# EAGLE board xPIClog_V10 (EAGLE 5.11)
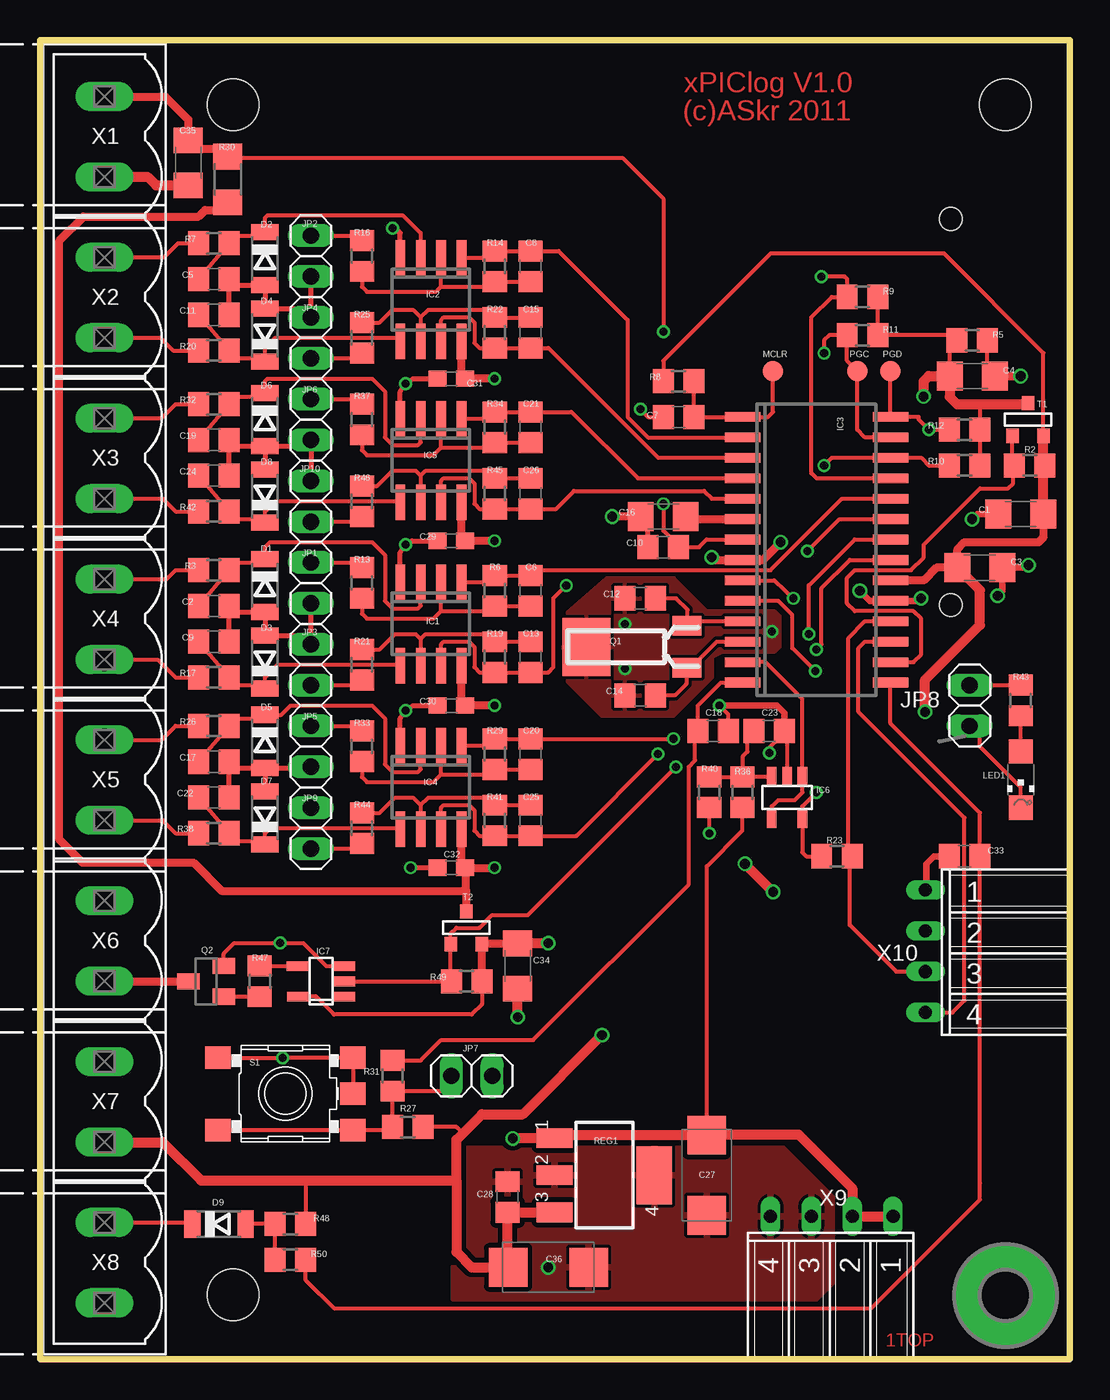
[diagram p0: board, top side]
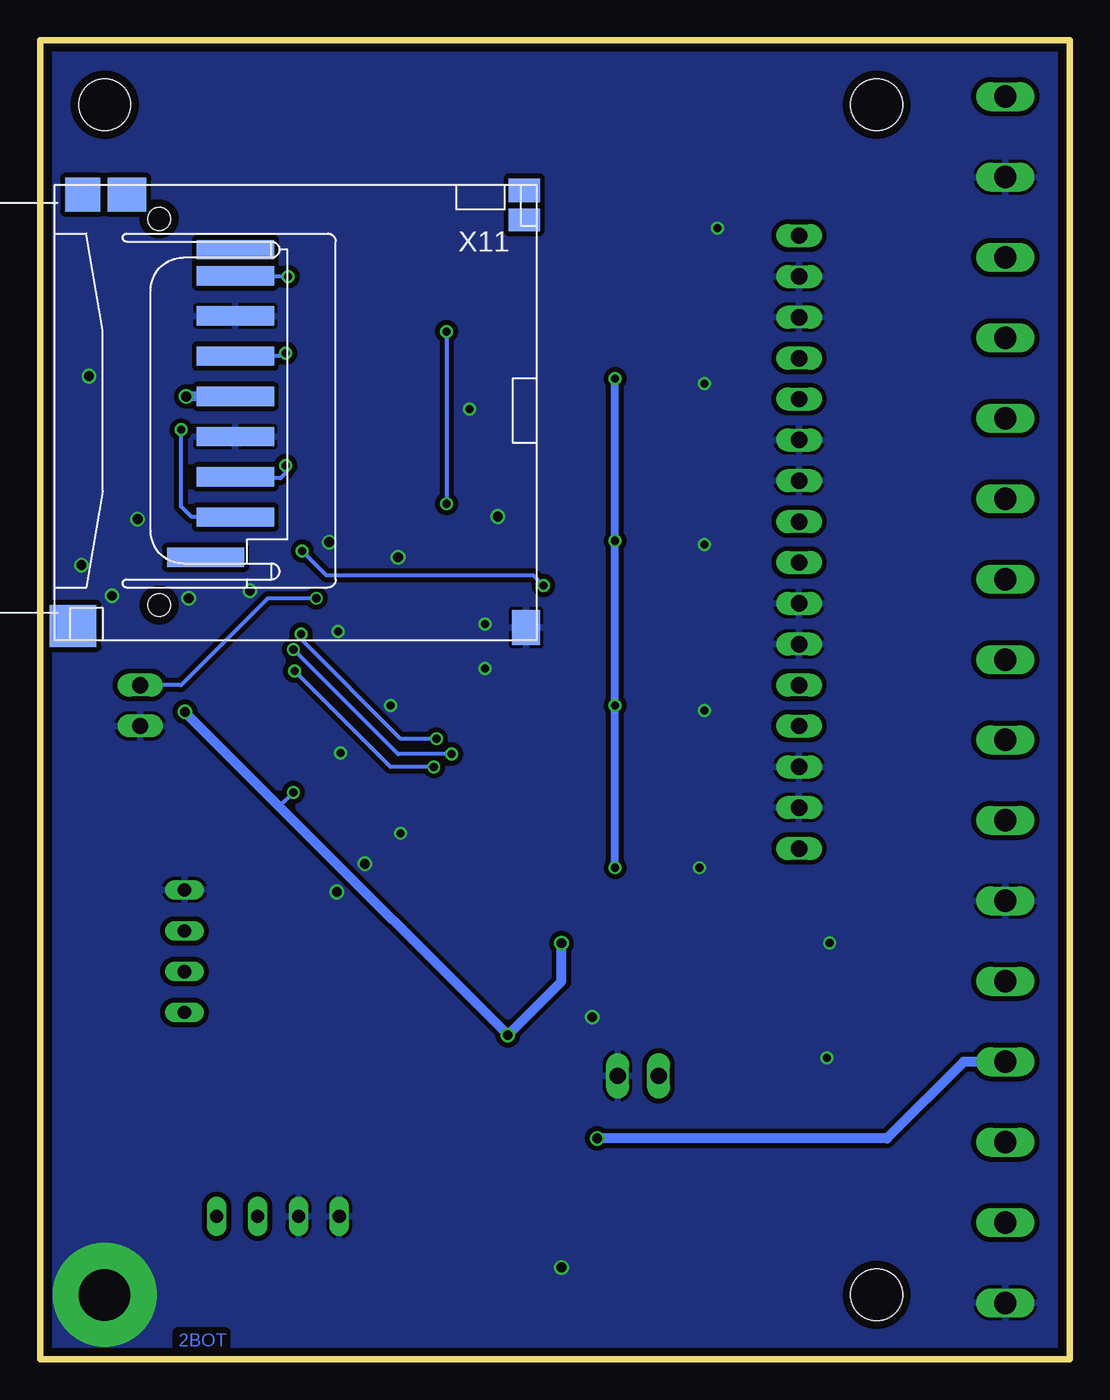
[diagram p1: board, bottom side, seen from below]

Size 64 x 82 mm. Coordinates in mm from the lower left corner, seen from the top.
Outline: 0,0 0,82 64,82 64,0 0,0
Copper layers (1*16): Top 0.035mm / dielectric 1.5mm / Bottom 0.035mm
Design rules "pcb-pool-2009": minimum track width 6mil, minimum drill 12mil, track to track 6mil, track to pad 6mil, pad to pad 6mil, via to via 6mil, smd to smd 6mil, copper to edge 20mil, drill to drill 8mil, minimum pad ring 8mil, minimum via ring 6mil, stop-mask expansion 3mil, vias tented up to drill 0mil, thermal gap 8mil
Holes 3.2 mm at 12,78 60,78 12,4
bRestrict: 3 lines

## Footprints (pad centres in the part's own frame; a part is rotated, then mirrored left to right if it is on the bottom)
C1206 = smd 1.6 x 1.8: 1 -1.4,0; 2 1.4,0
C0805 = smd 1.3 x 1.5: 1 -0.95,0; 2 0.95,0
SMC_C = smd 2.4 x 2.4: + -2.5,0; - 2.5,0
C0603 = smd 1.1 x 1: 1 -0.85,0; 2 0.85,0
SOD80-R = smd 1 x 1.7: A 1.65,0; C -1.65,0
SO08 = smd 0.6 x 2.2: 1 -1.905,-2.6; 2 -0.635,-2.6; 3 0.635,-2.6; 4 1.905,-2.6; 5 1.905,2.6; 6 0.635,2.6; 7 -0.635,2.6; 8 -1.905,2.6
AKKI_SO28W = smd 0.6 x 2.2: 1 -8.255,-4.6; 2 -6.985,-4.6; 3 -5.715,-4.6; 4 -4.445,-4.6; 5 -3.175,-4.6; 6 -1.905,-4.6; 7 -0.635,-4.6; 8 0.635,-4.6; 9 1.905,-4.6; 10 3.175,-4.6; 11 4.445,-4.6; 12 5.715,-4.6; 13 6.985,-4.6; 14 8.255,-4.6; 15 8.255,4.6; 16 6.985,4.6; 17 5.715,4.6; 18 4.445,4.6; 19 3.175,4.6; 20 1.905,4.6; 21 0.635,4.6; 22 -0.635,4.6; 23 -1.905,4.6; 24 -3.175,4.6; 25 -4.445,4.6; 26 -5.715,4.6; 27 -6.985,4.6; 28 -8.255,4.6
SOT23-5 = smd 0.6 x 1.2: 1 -0.95,-1.306; 2 0,-1.306; 3 0.95,-1.306; 4 0.95,1.306; 5 -0.95,1.306
AKKI_SOT235W = smd 0.6 x 1.4: 1 -0.95,-1.406; 2 0,-1.406; 3 0.95,-1.406; 5 -0.95,1.406 | smd 0.6 x 1.5: 4 0.95,1.406
1X02 = drill 1.016 long: 1 -1.27,0; 2 1.27,0
CHIPLED_1206 = smd 1.5 x 1.5: A 0,-1.75; C 0,1.75
B1,27 = smd 1.27 x 1.27: TP 0,0
AKKI_QUARTZ_MS1V-T1K = smd 1.8 x 1.2: 1 2.9,-1.3; 2 2.9,1.3 | smd 3 x 3.6: CASE -3.35,0
SOT23 = smd 1 x 1.4: 1 -0.95,-1.1; 2 0.95,-1.1; 3 0,1.1
R0805 = smd 1.3 x 1.5: 1 -0.95,0; 2 0.95,0
R1206 = smd 1.6 x 1.803: 1 -1.422,0; 2 1.422,0
AKKI_SOT223_4PIN = smd 1.219 x 2.235: 1 -2.311,-3.099; 2 0,-3.099; 3 2.311,-3.099 | smd 3.6 x 2.2: 4 0,3.099
SKHMPXE010 = smd 1.6 x 1.4: 1 -4.2,2.25; 2 4.2,2.25; 3 -4.2,-2.25; 4 4.2,-2.25; 5 4.2,0
SOT-23 = smd 0.787 x 0.889: 1 0.025,-1.016; 2 -0.94,1.016; 3 0.991,1.016
MSTBV2 = drill 1.397 long: 1 -2.5,0; 2 2.5,0
AKKI_FH1X4 = drill 0.813 long: 1 -5.08,0; 2 -2.54,0; 3 0,0; 4 2.54,0
AKKI_6173PACK2 = smd 4.8 x 1.2: P1 18.935,21.035; P2 18.935,18.535; P3 18.935,16.035; P4 18.935,13.535; P5 18.935,11.035; P6 18.935,8.535; P7 18.935,6.035; P8 18.935,4.41; P9 20.785,23.535 | smd 1.95 x 1.4: P_CD 0.975,2.55 | smd 1.95 x 1.45: P_COM 0.975,0.725 | smd 2.2 x 2.1: P_WP 28.425,1 | smd 1.75 x 2.2: PG1 0.875,27.9 | smd 2.9 x 2.6: PG2 29.025,27.8 | smd 2.4 x 2.1: PG3 25.675,1 | hole 1.4: 23.675,26.5; 23.675,2.5

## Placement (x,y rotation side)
C1  22u/6V3  [C1206]  60.96,52.55 0 top
C2  100n  [C0805]  10.79,46.83 0 top
C3  10u/6V3  [C1206]  58.42,49.21 180 top
C4  1u/6V3  [C1206]  57.94,61.12 0 top
C5  100n  [C0805]  10.8,67.15 0 top
C6  1n  [C0805]  30.48,47.78 90 top
C7  100n(*1*)  [C0805]  39.69,58.58 0 top
C8  1n  [C0805]  30.48,67.94 90 top
C9  100n  [C0805]  10.79,44.61 0 top
C10  100n  [C0805]  38.74,50.48 180 top
C11  100n  [C0805]  10.79,64.93 0 top
C12  8p2  [C0805]  37.31,47.31 0 top
C13  1n  [C0805]  30.48,43.66 270 top
C14  8p2  [C0805]  37.31,41.27 0 top
C15  1n  [C0805]  30.48,63.82 270 top
C16  10u/6V3  [C1206]  38.73,52.39 180 top
C17  100n  [C0805]  10.79,37.15 0 top
C18  100n  [C0805]  41.83,39.05 0 top
C19  100n  [C0805]  10.79,57.15 0 top
C20  1n  [C0805]  30.48,37.62 90 top
C21  1n  [C0805]  30.48,57.94 90 top
C22  100n  [C0805]  10.79,34.92 0 top
C23  1n  [C0805]  45.32,39.05 180 top
C24  100n  [C0805]  10.79,54.93 0 top
C25  1n  [C0805]  30.48,33.5 270 top
C26  1n  [C0805]  30.48,53.82 270 top
C27  22u;10V  [SMC_C]  41.44,11.45 270 top
C28  100n  [C0805]  29.05,10.1 90 top
C29  100n  [C0603]  25.56,50.88 180 top
C30  100n  [C0603]  25.56,40.64 180 top
C31  100n  [C0603]  25.56,60.96 180 top
C32  100n  [C0603]  25.56,30.56 180 top
C33  1n  [C0805]  57.47,31.27 180 top
C34  22u/6V3  [C1206]  29.69,24.45 90 top
C35  100n  [C1206]  9.21,74.37 90 top
C36  22u;10V  [SMC_C]  31.59,5.71 0 top
D1  LL4448  [SOD80-R]  13.97,48.1 270 top
D2  LL4448  [SOD80-R]  13.97,68.42 270 top
D3  LL4448  [SOD80-R]  13.97,43.34 90 top
D4  LL4448  [SOD80-R]  13.97,63.66 90 top
D5  LL4448  [SOD80-R]  13.97,38.42 270 top
D6  LL4448  [SOD80-R]  13.97,58.42 270 top
D7  LL4448  [SOD80-R]  13.97,33.66 90 top
D8  LL4448  [SOD80-R]  13.97,53.66 90 top
D9  LL103  [SOD80-R]  11.11,8.41 0 top
IC1  MCP6032  [SO08]  24.29,45.72 180 top
IC2  MCP6032  [SO08]  24.29,65.88 180 top
IC3  PIC18F27J13SO-28W  [AKKI_SO28W]  48.26,50.32 270 top
IC4  MCP6032  [SO08]  24.29,35.56 180 top
IC5  MCP6032  [SO08]  24.29,55.88 180 top
IC6  MCP6441  [SOT23-5]  46.43,34.92 180 top
IC7  NC7S14  [AKKI_SOT235W]  17.46,23.5 90 top
JP1  [1X02]  16.83,48.26 90 top
JP2  [1X02]  16.83,68.58 90 top
JP3  [1X02]  16.83,43.18 270 top
JP4  [1X02]  16.83,63.5 270 top
JP5  [1X02]  16.83,38.1 90 top
JP6  [1X02]  16.83,58.42 90 top
JP7  [1X02]  26.83,17.62 0 top
JP8  [1X02]  57.78,40.64 270 top
JP9  [1X02]  16.83,33.02 270 top
JP10  [1X02]  16.83,53.34 270 top
LED1  red  [CHIPLED_1206]  60.96,36.04 180 top
MCLR  [B1,27]  45.56,61.44 0 top
PGC  [B1,27]  50.8,61.44 0 top
PGD  [B1,27]  52.86,61.44 0 top
Q1  32768Hz  [AKKI_QUARTZ_MS1V-T1K]  37.31,44.29 0 top
Q2  BSS123  [SOT23]  10.32,23.5 90 top
R2  100k  [R0805]  61.52,55.56 0 top
R3  20k  [R0805]  10.79,49.05 180 top
R5  20k  [R0805]  57.94,63.34 180 top
R6  180k  [R0805]  28.26,47.78 270 top
R7  20k  [R0805]  10.79,69.37 180 top
R8  10k  [R0805]  39.69,60.8 180 top
R9  10k  [R0805]  51.12,66.04 0 top
R10  100k  [R0805]  57.47,55.56 0 top
R11  100k  [R0805]  51.12,63.66 0 top
R12  100k  [R0805]  57.47,57.78 0 top
R13  20k  [R0805]  20,48.26 90 top
R14  180k  [R0805]  28.26,67.94 270 top
R16  20k  [R0805]  20,68.58 90 top
R17  20k  [R0805]  10.79,42.39 180 top
R19  180k  [R0805]  28.26,43.66 90 top
R20  20k  [R0805]  10.79,62.71 180 top
R21  20k  [R0805]  20,43.18 270 top
R22  180k  [R0805]  28.26,63.82 90 top
R23  100k  [R0805]  49.53,31.27 180 top
R25  20k  [R0805]  20,63.5 270 top
R26  20k  [R0805]  10.79,39.37 180 top
R27  100k  [R0805]  22.86,14.45 180 top
R29  180k  [R0805]  28.26,37.62 270 top
R30  22E  [R1206]  11.67,73.34 270 top
R31  20k  [R0805]  21.91,17.62 90 top
R32  20k  [R0805]  10.79,59.37 180 top
R33  20k  [R0805]  20,38.1 90 top
R34  180k  [R0805]  28.26,57.94 270 top
R36  3M3  [R0805]  43.66,35.24 270 top
R37  20k  [R0805]  20,58.42 90 top
R38  20k  [R0805]  10.79,32.7 180 top
R40  2M2  [R0805]  41.59,35.24 90 top
R41  180k  [R0805]  28.26,33.5 90 top
R42  20k  [R0805]  10.79,52.7 180 top
R43  470E  [R0805]  60.96,40.96 90 top
R44  20k  [R0805]  20,33.02 270 top
R45  180k  [R0805]  28.26,53.82 90 top
R46  20k  [R0805]  20,53.34 270 top
R47  20k  [R0805]  13.65,23.5 270 top
R48  100k  [R0805]  15.56,8.41 180 top
R49  2M2  [R0805]  26.51,23.5 0 top
R50  20k  [R0805]  15.56,6.19 0 top
REG1  MCP1703-33  [AKKI_SOT223_4PIN]  35.09,11.45 270 top
S1  SKHMPSE010  [SKHMPXE010]  15.24,16.51 0 top
T1  DMG3415U  [SOT-23]  61.44,58.42 180 top
T2  DMG3415U  [SOT-23]  26.51,26.83 180 top
X1  [MSTBV2]  4,76 90 top
X2  [MSTBV2]  4,66 90 top
X3  [MSTBV2]  4,56 90 top
X4  [MSTBV2]  4,46 90 top
X5  [MSTBV2]  4,36 90 top
X6  [MSTBV2]  4,26 90 top
X7  [MSTBV2]  4,16 90 top
X8  [MSTBV2]  4,6 90 top
X9  [AKKI_FH1X4]  47.94,8.89 180 top
X10  [AKKI_FH1X4]  55.03,24.1 270 top
X11  SD-CARD  [AKKI_6173PACK2]  32.93,73.39 180 bottom

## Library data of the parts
C1 C3 C4 C16 C34 C35 R30 = rcl; SIZE: 1206
C2 C5-C15 C17-C26 C28 C33 R2 R3 R5-R14 R16 R17 R19-R23 R25-R27 R29 R31-R34 R36-R38 R40-R50 = rcl
C27 C36 = rcl; TYPE: tant.
C29-C32 = rcl; SIZE: 0603
D1-D9 IC1-IC7 Q1 REG1 T1 T2 X9-X11 = Akki
JP1-JP10 = pinhead
LED1 = led
MCLR PGC PGD = testpad
Q2 = transistor-small-signal
S1 = switch
X1-X8 = con-phoenix-500; OC_FARNELL: unknown; OC_NEWARK: unknown

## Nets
+3V3: C1.2 C3.2 C28.1 C34.2 C36.+ IC3.20 IC6.5 IC7.5 R2.2 R8.2 R23.2 R27.1 R48.1 R49.2 REG1.3 T1.2 T2.2 X7.1
+UB: C29.1 C30.1 C31.1 C32.1 IC1.8 IC2.8 IC4.8 IC5.8 R30.2 T2.1
AD_EXT: IC3.13 IC6.1 IC6.4
GND: C1.1 C2.2 C3.1 C4.2 C5.2 C7.1 C9.2 C10.2 C11.2 C12.1 C14.1 C16.2 C17.2 C18.2 C19.2 C22.2 C23.1 C24.2 C27.- C28.2 C29.2 C30.2 C31.2 C32.2 C33.2 C34.1 C35.1 C36.- D1.A D2.A D3.A D4.A D5.A D6.A D7.A D8.A IC1.4 IC2.4 IC3.8 IC3.19 IC4.4 IC5.4 IC6.2 IC7.3 JP1.1 JP2.1 JP3.1 JP4.1 JP5.1 JP6.1 JP7.2 JP8.2 JP9.1 JP10.1 LED1.C Q1.CASE Q2.2 R5.1 R40.1 REG1.2 REG1.4 S1.1 S1.2 S1.5 X1.1 X6.2 X8.1 X9.3 X9.4 X10.1 X11.P3 X11.P6 X11.PG1
IN1: R7.2 X2.2
IN2: R20.2 X2.1
IN3: R32.2 X3.2
IN4: R42.2 X3.1
IN5: R3.2 X4.2
IN6: R17.2 X4.1
IN7: R26.2 X5.2
IN8: R38.2 X5.1
LED: IC3.9 JP8.1 R43.2
N$1: C16.1 IC3.6
N$2: C7.2 IC3.1 MCLR.TP R8.1
N$3: C12.2 IC3.11 Q1.2
N$4: C14.2 IC3.12 Q1.1
N$5: C15.1 IC2.6 R22.2 R25.1
N$6: C8.1 IC2.2 R14.2 R16.1
N$7: JP2.2 R16.2
N$8: C5.1 D2.C IC2.3 R7.1
N$9: JP4.2 R25.2
N$10: C11.1 D4.C IC2.5 R20.1
N$11: C4.1 R5.2 R9.2 R10.2 R11.2 R12.2 T1.1 X11.P4
N$12: C10.1 C35.2 IC3.7 R30.1 X1.2
N$13: C21.1 IC5.2 R34.2 R37.1
N$14: JP6.2 R37.2
N$15: C19.1 D6.C IC5.3 R32.1
N$16: JP7.1 R27.2 R31.1 S1.3 S1.4
N$17: C26.1 IC5.6 R45.2 R46.1
N$18: JP10.2 R46.2
N$19: C24.1 D8.C IC5.5 R42.1
N$20: C23.2 IC6.3 R36.1 R40.2
N$21: C6.1 IC1.2 R6.2 R13.1
N$22: JP1.2 R13.2
N$23: C2.1 D1.C IC1.3 R3.1
N$24: D9.A R48.2 R50.1
N$25: C13.1 IC1.6 R19.2 R21.1
N$26: JP3.2 R21.2
N$27: C9.1 D3.C IC1.5 R17.1
N$28: Q2.1 R47.2
N$29: C20.1 IC4.2 R29.2 R33.1
N$30: JP5.2 R33.2
N$31: C17.1 D5.C IC4.3 R26.1
N$32: Q2.3 X6.1
N$33: C25.1 IC4.6 R41.2 R44.1
N$34: JP9.2 R44.2
N$35: C22.1 D7.C IC4.5 R38.1
N$36: IC7.4 R47.1
N$37: IC3.17 X10.4
N$38: IC3.18 R23.1 X10.3
N$39: D9.C X8.2
N$40: LED1.A R43.1
OP1: C8.2 IC2.1 IC3.2 R14.1
OP2: C15.2 IC2.7 IC3.3 R22.1
OP3: C21.2 IC3.4 IC5.1 R34.1
OP4: C26.2 IC3.5 IC5.7 R45.1
OP5: C6.2 IC1.1 IC3.24 R6.1
OP6: C13.2 IC1.7 IC3.23 R19.1
OP7: C20.2 IC3.22 IC4.1 R29.1
OP8: C25.2 IC3.21 IC4.7 R41.1
POWOUT: IC3.10 IC7.2 R49.1 T2.3
PUSHBUT: C18.1 IC3.14 R31.2
SD_CLK: IC3.27 PGC.TP R11.1 X11.P5
SD_CS: IC3.28 PGD.TP R12.1 X11.P1
SD_DI: IC3.26 R10.1 X11.P2
SD_DO: IC3.25 R9.1 X11.P7
SD_POW: IC3.16 R2.1 T1.3
TRIG: C33.1 IC3.15 R50.2
UBEXT: C27.+ R36.2 REG1.1 X7.2 X9.1 X9.2

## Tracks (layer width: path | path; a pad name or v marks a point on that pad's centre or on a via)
+3V3  (via drill 0.5, 0.6)
  Top 0.254: R48.1 16.51,11.11 | R27.1 25.88,14.45 26.27,14.05 | IC7.5 17.14,22.55 18.26,21.43 26.83,21.43 27.46,22.07 R49.2 | R23.2 47.62,31.27 47.38,31.52 IC6.5 47.38,34.37 v48.26,35.24 | R23.2 | T1.2 62.38,62.56 56.2,68.74 45.4,68.74 38.73,62.07 R8.2
  Top 0.508: C3.2 57.02,49.69 57.02,50.35 57.47,50.8 62.07,50.8 62.39,51.12 62.39,52.52 C1.2 | C34.2 28.96,25.81 T2.2 R49.2 | IC3.20 54.93,48.42 55.72,49.21 C3.2 | C3.2
  Top 0.61: C1.2 62.36,55.46 R2.2 62.38,55.65 T1.2 | REG1.3 29.06,9.13 C28.1 29.05,5.75 C36.+ 26.83,5.71 25.88,6.67 25.88,11.11 | 25.88,11.11 25.88,13.65 26.27,14.05 27.46,15.24 30,15.24 v34.92,20.16 | v34.92,20.16 | C3.2 58.42,47.81 58.42,45.64 55.01,42.23 v55.01,40.24 | X7.1 7.61,13.5 10,11.11 16.51,11.11 25.88,11.11 | v31.59,25.88 31.56,25.85 C34.2
  Bottom 0.254: 49.13,34.37 v48.26,35.24
  Bottom 0.61: v55.01,40.24 49.13,34.37 v34.92,20.16 31.59,23.5 v31.59,25.88
+UB  (via drill 0.5)
  Top 0.508: 26.49,29.13 T2.1 | 26.49,29.13 26.49,30.48 C32.1 | IC4.8 26.19,30.77 C32.1 | IC2.8 26.19,61.17 C31.1 v28.26,60.96 | v28.26,50.88 C29.1 26.19,51.09 IC5.8 | v28.26,40.64 C30.1 26.19,40.85 IC1.8 | C32.1 v28.26,30.56 | 26.49,29.13 11.27,29.13 9.53,30.88 2.62,30.88 1.19,32.31 1.19,69.53 2.7,71.04 9.84,71.04 10.24,71.44 11.26,71.44 R30.2
  Bottom 0.508: v28.26,60.96 v28.26,50.88 v28.26,40.64 v28.26,30.56
AD_EXT
  Top 0.254: IC3.13 45.09,43.34 47.38,41.04 IC6.1 47.39,35.24 46.91,34.77 45.88,34.77 45.48,34.37 IC6.4
GND  (via drill 0.5, 0.6, 3.2 pad 6.45)
  Top 0.254: C7.1 37.78,58.58 v37.31,59.05 | R5.1 58.89,61.57 C4.2 | IC7.3 17.78,24.45 16.35,25.88 v14.92,25.88 12.06,25.88 11.42,25.23 Q2.2 | S1.1 11.07,18.73 v15.08,18.73 15.11,18.76 S1.2 S1.5 | LED1.C 60.96,35.56 58.42,38.1 58.42,38.73 JP8.2 | v41.59,32.7 R40.1 | IC6.2 46.43,38.65 46.36,38.83 | 46.36,38.83 C23.1 | 46.36,38.83 46.26,38.73 46.12,38.73 45.8,38.42 45.72,38.42 45.32,38.02 v45.32,37.7 | C18.2 42.78,40.09 v42.23,40.64
  Top 0.305: C11.2 11.74,66.83 | 11.74,66.83 C5.2 | C11.2 | 11.74,66.83 11.81,66.77 D2.A D4.A 16.29,65.31 JP4.1 JP2.1 | v21.91,70.33 22.07,70.33 22.38,70.01 IC2.4 | C31.2 23.18,60.96 v22.7,60.64 22.38,60.17 IC5.4 | C29.2 23.1,50.88 v22.7,50.64 22.38,50.16 IC1.4 | IC4.4 22.38,39.85 v22.7,40.32 23.18,40.64 C30.2 | C24.2 C19.2 12.12,56.77 D6.A | D6.A D8.A | D6.A 16.45,56.77 JP6.1 JP10.1 | C9.2 11.74,46.51 | 11.74,46.51 C2.2 | D1.A 11.81,46.45 11.74,46.51 | D1.A D3.A 16.29,44.99 JP3.1 JP1.1 | D1.A | C22.2 11.74,36.83 | 11.74,36.83 C17.2 | D5.A 11.81,36.77 11.74,36.83 | D5.A D7.A | D5.A 16.77,36.77 JP5.1 | C10.2 37.78,51.94 C16.2 | C32.2 v23.02,30.56
  Top 0.406: v54.77,47.31 54.61,47.15 IC3.19 51.59,47.15 v50.96,47.78 | C1.1 58.26,52.55 v57.94,52.23 | v61.44,49.37 61.28,49.21 C3.1 59.82,47.76 v59.53,47.47 | C33.2 55.56,31.27 55.09,30.8 55.09,29.23 X10.1 | v42.23,40.64 45.8,40.64 46.28,40.16 46.28,38.97
  Top 0.508: C4.2 v60.96,61.12 | C4.2 | v41.75,49.85 41.91,49.69 IC3.8 44.93,49.69 v46.04,50.8 | C16.2 v35.56,52.39 | v35.56,52.39
  Top 0.61: C27.- 41.49,8.89 | C35.1 7.19,72.97 6.67,73.5 X1.1 | v29.69,21.27 C34.1 | v29.69,21.27 | v43.81,30.8 | v45.56,29.05 v43.81,30.8
  other vias: 60,4 36.35,45.72 36.35,42.94 45.48,45.24 31.59,5.71
  pour Top (isolate 0.203): 32.54,46.2 35.24,48.58 39.37,48.58 41.43,46.51 45.64,46.51 45.96,46.2 45.96,44.29 45.64,43.97 42.39,43.97 41.75,43.66 41.75,42.39 39.37,40.01 34.93,40.01 32.54,42.39
  pour Top (isolate 0.305): 25.72,13.1 46.2,13.1 49.21,10.08 49.21,4.76 48.18,3.73 25.72,3.73
  pour Bottom (isolate 0.305): 0.64,81.28 63.5,81.28 63.5,0.64 0.64,0.64
IN1
  Top 0.254: X2.2 7.7,68.5 8.57,69.37 R7.2 | R7.2
IN2
  Top 0.254: X2.1 7.46,63.5 8.26,62.71 R20.2 | R20.2
IN3
  Top 0.254: X3.2 7.54,58.5 8.41,59.37 R32.2
IN4
  Top 0.254: X3.1 7.62,53.5 8.41,52.7 R42.2
IN5
  Top 0.254: X4.2 7.86,48.5 8.41,49.05 R3.2
IN6
  Top 0.254: X4.1 7.3,43.5 8.41,42.39 R17.2 | R17.2
IN7
  Top 0.254: X5.2 7.54,38.5 8.41,39.37 R26.2
IN8
  Top 0.254: X5.1 7.62,33.5 8.41,32.7 R38.2
LED  (via drill 0.5)
  Top 0.254: IC3.9 45.64,48.42 v46.83,47.31 | R43.2 JP8.1
  Bottom 0.254: JP8.1 55.24,41.91 49.85,47.31 v46.83,47.31
N$1
  Top 0.508: IC3.6 40.29,52.23 C16.1
N$2
  Top 0.254: C7.2 IC3.1 45.24,58.58 45.56,58.9 MCLR.TP | C7.2 R8.1 | C7.2
N$3
  Top 0.254: IC3.11 40.49,45.88 40.41,45.79 | Q1.2 40.41,45.79 | C12.2 39.53,47.31 40.24,46.59 40.24,45.96 40.41,45.79
N$4
  Top 0.254: IC3.12 42.07,44.61 40.8,43.34 40.55,43.34 Q1.1 40.16,42.95 40.16,41.99 39.45,41.27 C14.2
N$5
  Top 0.254: R25.1 21.11,64.45 21.91,65.25 23.18,65.25 23.65,64.77 | C15.1 R22.2 27.78,65.25 24.13,65.25 23.65,64.77 | 23.65,64.77 IC2.6
N$6
  Top 0.254: R16.1 20,66.67 20.32,66.36 24.61,66.36 24.92,66.67 | 24.92,66.67 IC2.2 | 24.92,66.67 27.78,66.67 27.94,67 R14.2 C8.1
N$7
  Top 0.254: R16.2 19.68,69.85 JP2.2
N$8
  Top 0.254: C5.1 R7.1 12.22,69.85 13.75,69.85 D2.C 13.97,70.96 14.13,71.12 22.54,71.12 23.65,70.01 IC2.3
N$9
  Top 0.254: R25.2 19.68,62.23 JP4.2
N$10
  Top 0.254: C11.1 R20.1 12.22,62.23 13.75,62.23 D4.C 13.97,62.87 14.61,63.5 22.16,63.5 IC2.5
N$11  (via drill 0.6)
  Top 0.254: R10.2 R12.2 58.42,59.37 | C4.1 56.54,62.89 R5.2 56.68,63.66 R11.2 R9.2
  Top 0.61: v54.93,59.85 54.93,60.8 55.24,61.12 C4.1 | C4.1 | C4.1 56.54,59.82 56.99,59.37 58.42,59.37 61.35,59.37 T1.1
  Bottom 0.61: X11.P4 54.92,59.86 v54.93,59.85
N$12  (via drill 0.5)
  Top 0.254: IC3.7 41.43,50.96 40.96,50.48 40.32,50.48 C10.1 39.69,50.56 38.73,51.51 v38.73,53.18 | v38.73,63.9 38.73,72.15 36.2,74.69 11.99,74.69 R30.1
  Top 0.508: R30.1 11.19,75.25 9.84,75.25 9.32,75.77 C35.2 9.21,77.07 7.78,78.5 X1.2
  Bottom 0.254: v38.73,63.9 v38.73,53.18
N$13
  Top 0.254: R37.1 20,56.52 20.32,56.2 24.45,56.2 24.92,56.67 | C21.1 R34.2 28.1,56.99 27.78,56.67 24.92,56.67 | 24.92,56.67 IC5.2
N$14
  Top 0.254: JP6.2 19.68,59.69 R37.2
N$15
  Top 0.254: C19.1 R32.1 12.22,59.85 13.75,59.85 D6.C 13.97,60.8 14.13,60.96 20.64,60.96 21.43,60.17 21.43,57.31 21.91,56.83 23.5,56.83 23.65,56.99 IC5.3
N$16
  Top 0.254: S1.3 S1.4 21.72,14.26 R27.2 R31.1 25.09,16.67 25.24,16.83 25.24,17.3 JP7.1
N$17
  Top 0.254: 23.65,54.93 23.97,55.24 27.78,55.24 R45.2 C26.1 | 23.65,54.93 IC5.6 | R46.1 20.95,54.29 21.91,55.24 23.34,55.24 23.65,54.93
N$18
  Top 0.254: JP10.2 19.68,52.07 R46.2
N$19
  Top 0.254: C24.1 R42.1 12.22,52.23 13.75,52.23 D8.C 13.97,52.7 14.61,53.34 22.32,53.34 IC5.5
N$20
  Top 0.254: R40.2 R36.1 | R36.1 | 43.7,36.23 IC6.3 | R36.1 43.7,36.23 | 43.7,36.23 43.7,37.5 43.97,37.78 43.97,38.57 C23.2
N$21
  Top 0.254: R13.1 20,46.35 20.32,46.04 24.45,46.04 24.92,46.51 | 24.92,46.51 IC1.2 | 24.92,46.51 27.62,46.51 27.94,46.83 R6.2 C6.1
N$22
  Top 0.254: JP1.2 19.68,49.53 R13.2
N$23
  Top 0.254: C2.1 R3.1 12.22,49.53 13.75,49.53 D1.C 13.97,50.48 14.29,50.8 20.64,50.8 21.43,50.01 21.43,47.15 21.91,46.67 23.5,46.67 23.65,46.83 IC1.3
N$24
  Top 0.254: D9.A R48.2 R50.1
N$25
  Top 0.254: 23.65,44.77 23.97,45.09 27.78,45.09 R19.2 C13.1 | 23.65,44.77 IC1.6 | R21.1 21.11,44.13 22.07,45.09 23.34,45.09 23.65,44.77
N$26
  Top 0.254: JP3.2 19.68,41.91 R21.2
N$27
  Top 0.254: C9.1 R17.1 12.22,41.91 13.75,41.91 D3.C 13.97,42.39 14.76,43.18 22.32,43.18 IC1.5
N$28
  Top 0.254: Q2.1 R47.2
N$29
  Top 0.254: R29.2 28.1,36.67 27.78,36.35 24.92,36.35 | R33.1 20,36.2 20.32,35.88 24.45,35.88 24.92,36.35 | 24.92,36.35 IC4.2 | IC4.2 | R29.2 C20.1 | R29.2
N$30
  Top 0.254: JP5.2 19.68,39.37 R33.2
N$31
  Top 0.254: C17.1 R26.1 12.22,39.85 13.75,39.85 D5.C 14.98,40.07 15.56,40.64 20.64,40.64 21.43,39.85 21.43,36.99 21.91,36.51 23.5,36.51 23.65,36.67 IC4.3 | IC4.3 | IC4.3
N$32
  Top 0.508: X6.1 Q2.3
N$33
  Top 0.254: 23.65,34.45 24.13,34.92 27.78,34.92 R41.2 C25.1 | 23.65,34.45 IC4.6 | IC4.6 | R44.1 21.11,33.97 22.07,34.92 23.18,34.92 23.65,34.45 | C25.1
N$34
  Top 0.254: JP9.2 19.68,31.75 R44.2
N$35
  Top 0.254: C22.1 R38.1 12.22,32.23 13.75,32.23 D7.C 13.97,32.7 14.29,33.02 22.32,33.02 IC4.5
N$36
  Top 0.254: R47.1 IC7.4 | IC7.4
N$37
  Top 0.254: X10.4 56.72,21.56 57.47,22.3 57.47,33.66 50.88,40.24 50.88,44.21 51.28,44.61 IC3.17 | IC3.17
N$38
  Top 0.254: IC3.18 51.28,45.88 50.24,44.85 50.24,31.35 R23.1 50.32,31.27 50.32,26.99 53.21,24.1 X10.3
N$39
  Top 0.254: X8.2 9.38,8.5 D9.C
N$40
  Top 0.254: LED1.A R43.1 | R43.1
OP1
  Top 0.254: IC2.1 27.84,68.48 R14.1 C8.2 32.23,68.9 36.51,64.61 36.51,58.58 37.78,57.31 IC3.2
OP2
  Top 0.254: IC2.7 24.92,64.61 25.08,64.77 26.67,64.77 26.99,64.45 26.99,63.18 27.3,62.87 R22.1 C15.2 31.59,62.87 38.42,56.04 IC3.3
OP3
  Top 0.254: IC5.1 27.84,58.48 R34.1 C21.2 33.02,58.9 37.15,54.77 IC3.4
OP4
  Top 0.254: IC5.7 24.92,54.61 25.08,54.77 26.67,54.77 26.99,54.45 26.99,53.18 27.3,52.87 R45.1 C26.2 32.07,52.86 33.18,53.98 41.27,53.98 41.75,53.5 IC3.5
OP5
  Top 0.254: IC1.1 27.84,48.32 R6.1 C6.2 30.8,49.05 45.4,49.05 49.85,53.5 IC3.24
OP6  (via drill 0.5)
  Top 0.254: IC1.7 24.92,44.45 25.08,44.61 26.67,44.61 26.99,44.29 26.99,43.02 27.3,42.71 R19.1 C13.2 31.59,42.71 31.91,43.02 31.91,47.31 v32.7,48.1 | IC3.23 49.69,52.23 v47.7,50.24
  Bottom 0.254: v47.7,50.24 46.2,48.74 33.34,48.74 v32.7,48.1
OP7  (via drill 0.5)
  Top 0.254: IC4.1 27.84,38.16 R29.1 C20.2 | C20.2 | IC3.22 50.64,50.96 47.78,48.1 v47.78,45.09 | v39.37,38.58 C20.2
  Bottom 0.254: v47.78,45.09 47.78,44.77 41.59,38.58 v39.37,38.58
OP8  (via drill 0.5)
  Top 0.254: IC4.7 24.92,34.29 25.08,34.45 26.67,34.45 26.99,34.13 26.99,32.86 27.3,32.55 R41.1 C25.2 33.34,32.55 v38.42,37.62 | IC4.7 | IC3.21 50.32,49.69 48.58,47.94 48.58,44.45 v48.26,44.13
  Bottom 0.254: v48.26,44.13 41.75,37.62 v38.42,37.62
POWOUT  (via drill 0.5)
  Top 0.254: IC7.2 R49.1 | R49.1 | R49.1 25.52,23.54 T2.3 25.52,26.47 25.88,26.83 27.3,26.83 28.1,27.62 30.32,27.62 v39.53,36.83 | v48.18,42.78 46.75,44.21 46.75,46.28 45.88,47.15 IC3.10
  Bottom 0.254: v39.53,36.83 42.23,36.83 v48.18,42.78
PUSHBUT
  Top 0.254: R31.2 23.65,18.57 24.92,19.84 30.64,19.84 40.32,29.53 40.32,36.83 40.72,37.23 40.72,38.73 C18.1 40.88,40.64 42.31,42.07 IC3.14 | IC3.14
SD_CLK  (via drill 0.5)
  Top 0.254: IC3.27 51.28,57.31 50.8,57.78 PGC.TP | PGC.TP | PGC.TP 50.16,62.07 R11.1 49.05,63.66 48.74,63.34 v48.74,62.55
  Bottom 0.254: X11.P5 48.93,62.36 v48.74,62.55
SD_CS  (via drill 0.5)
  Top 0.254: PGD.TP IC3.28 54.61,58.58 54.61,58.42 v55.24,57.78 R12.1 | R12.1
  Bottom 0.254: X11.P1 54.58,52.36 55.24,53.02 v55.24,57.78
SD_DI  (via drill 0.5)
  Top 0.254: R10.1 55.24,55.56 54.77,56.04 IC3.26 49.21,56.04 v48.74,55.56
  Bottom 0.254: X11.P2 51.48,55.24 50.96,55.24 50.48,54.77 49.05,54.77 48.74,55.09 v48.74,55.56
SD_DO  (via drill 0.5)
  Top 0.254: R9.1 49.21,66.04 47.94,64.77 47.94,55.09 48.26,54.77 IC3.25 | R9.1 | R9.1 50.17,67.15 50.01,67.31 v48.58,67.31
  Bottom 0.254: v48.58,67.31 51.82,67.31 X11.P7
SD_POW
  Top 0.254: T1.3 60.45,55.68 R2.1 60.48,55.48 60.48,54.45 60.17,54.13 58.42,54.13 54.93,50.64 54.93,49.85 54.13,49.05 50.64,49.05 50.16,48.58 50.16,46.99 50.64,46.51 54.29,46.51 54.77,46.04 54.77,43.81 54.29,43.34 IC3.16
TRIG
  Top 0.254: R50.2 16.51,4.92 18.26,3.17 51.67,3.17 58.42,9.92 58.42,10.96 | IC3.15 52.86,39.53 58.42,33.97 C33.1 58.42,10.96 | 58.42,10.96 58.42,10.95
UBEXT  (via drill 0.6)
  Top 0.254: C27.+ 41.44,30.64 43.66,32.86 R36.2
  Top 0.61: X9.1 X9.2 50.48,10.64 47.15,13.97 41.46,13.97 C27.+ 32.17,13.95 REG1.1 29.39,13.76 v29.37,13.73
  Bottom 0.61: v29.37,13.73 11.35,13.73 6.59,18.49 X7.2

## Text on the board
Top: xPIClog V1.0 | (c)ASkr 2011 | 1TOP
Bottom: 2BOT
tDocu: +UB switched | GND | IN1 | IN2 | IN3 | IN4 | IN5 | IN6 | ext. LED | IN7 | GND | IN8 | GND | GND | GND switched | RX | TX | +UBext | ext. pushbutton | +3V3 | TRIG | GND | GND | GND | +UBext | +UBext | xPIClog V1.0 | www.askrprojects.net
bDocu: xPIClog V1.0 | www.askrprojects.net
